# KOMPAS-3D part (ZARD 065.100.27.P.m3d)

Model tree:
1. Булева операция:1
2. Булева операция:2
3. Булева операция:3
4. Булева операция:4
5. Булева операция:5
6. Булева операция:6
7. Булева операция:7
8. Булева операция:8
9. Булева операция:9
10. Булева операция:10
11. Булева операция:11
12. Булева операция:12
13. Булева операция:13  (labels: C:\Program Files\ASCON\KOMPAS-3D V13\Sys\graphic.lyt)
